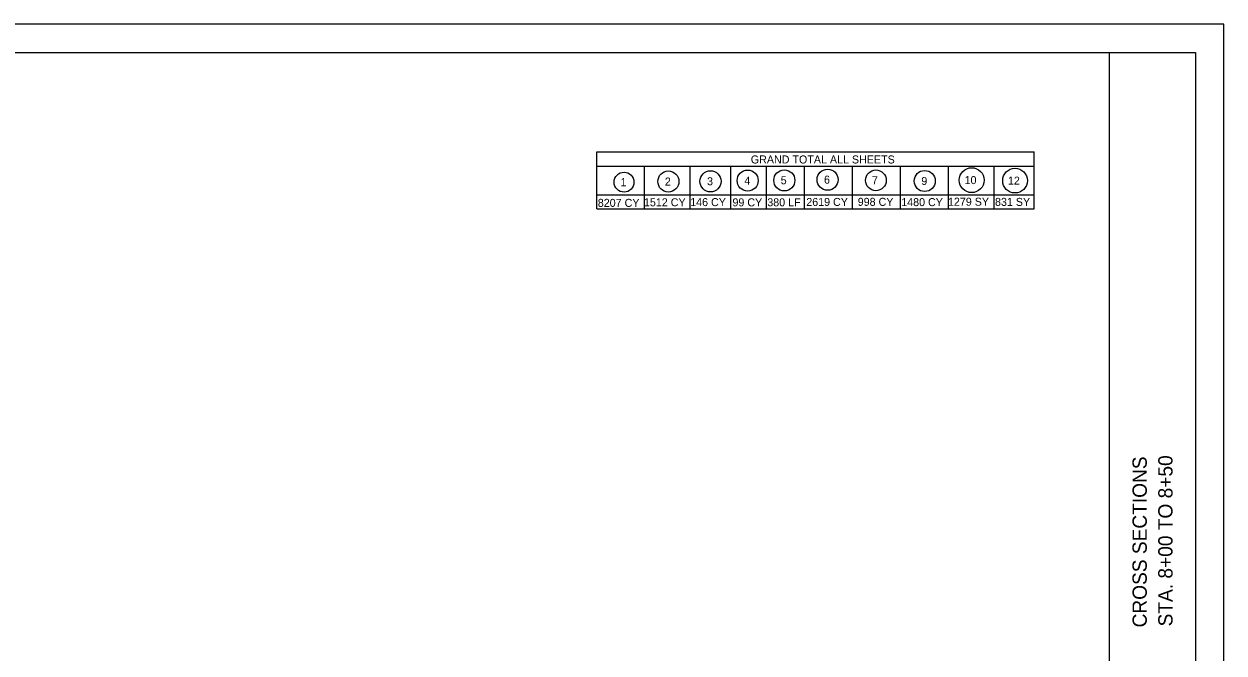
# Model space of a CAD drawing. Extents: x -31.8 to 34, y 0 to 22.
# Drawn here: x 13.01 to 34, y 11 to 22 of the extents above; entities that cross this region are included whole.
import ezdxf

# ---------------------------------------------------------------- set-up
doc = ezdxf.new("R2010")
doc.units = 0
for name, color, linetype in [('CS-ALGN-TEXT', 7, 'Continuous'), ('CS-ANNO', 7, 'Continuous'), ('CS-ANNO-MATC', 7, 'Continuous'), ('CS-ANNO-MATC-TEXT', 7, 'Continuous')]:
    doc.layers.add(name, color=color, linetype=linetype)

msp = doc.modelspace()

# ---------------------------------------------------------------- linework, layer by layer
at = {"layer": 'CS-ALGN-TEXT'}
for p, q in [((23.033, 18.765), (23.033, 19.765)), ((23.033, 19.765), (30.681, 19.765)), ((30.681, 18.765), (30.681, 19.765)), ((23.033, 19.515), (30.681, 19.515)), ((23.866, 18.764), (23.866, 19.514)), ((24.664, 18.765), (24.664, 19.515)), ((25.374, 18.765), (25.374, 19.515)), ((25.999, 18.765), (25.999, 19.515)), ((26.662, 18.765), (26.662, 19.515)), ((27.504, 18.765), (27.504, 19.515)), ((28.34, 18.765), (28.34, 19.515)), ((29.179, 18.765), (29.179, 19.515)), ((29.982, 18.765), (29.982, 19.515)), ((23.033, 19.015), (30.681, 19.015)), ((23.033, 18.765), (30.681, 18.765))]:
    msp.add_line(p, q, dxfattribs=at)
at = {"layer": 'CS-ANNO'}
msp.add_lwpolyline([(0, 0), (34, 0), (34, 22), (0, 22)], close=True, dxfattribs=at)
at = {"layer": 'CS-ANNO-MATC'}
msp.add_line((32, 0.5), (32, 21.5), dxfattribs=at)
msp.add_lwpolyline([(1.5, 21.5), (33.5, 21.5), (33.5, 0.5), (1.5, 0.5)], close=True, dxfattribs=at)
at = {"layer": 'CS-ANNO-MATC-TEXT'}
for centre, radius in [((23.507, 19.234), 0.174), ((24.282, 19.246), 0.184), ((25.019, 19.249), 0.185), ((25.669, 19.262), 0.184), ((26.31, 19.265), 0.184), ((27.067, 19.277), 0.184), ((27.912, 19.266), 0.181), ((28.766, 19.254), 0.184), ((29.587, 19.269), 0.218), ((30.345, 19.261), 0.216)]:
    msp.add_circle(centre, radius, dxfattribs=at)

# ---------------------------------------------------------------- texts
at = {"layer": 'CS-ALGN-TEXT'}
msp.add_text('GRAND TOTAL ALL SHEETS', height=0.14, dxfattribs=at).set_placement((25.724, 19.561))
for s, p in [('CROSS SECTIONS', (32.65, 11.447)), ('STA. 8+00 TO 8+50', (33.1, 11.465))]:
    msp.add_text(s, height=0.25, rotation=90, dxfattribs=at).set_placement(p)
at = {"layer": 'CS-ANNO-MATC-TEXT'}
for s, p in [('2', (24.221, 19.175)), ('3', (24.959, 19.18)), ('4', (25.612, 19.192)), ('5', (26.247, 19.197)), ('6', (27.004, 19.208)), ('7', (27.842, 19.197)), ('9', (28.706, 19.185)), ('10', (29.463, 19.2)), ('12', (30.221, 19.19)), ('1', (23.445, 19.164)), ('8207 CY', (23.048, 18.802)), ('1512 CY', (23.855, 18.812)), ('146 CY', (24.664, 18.815)), ('99 CY', (25.403, 18.811)), ('380 LF', (26.012, 18.812)), ('2619 CY', (26.694, 18.818)), ('998 CY', (27.594, 18.82)), ('1480 CY', (28.355, 18.815)), ('1279 SY', (29.172, 18.822)), ('831 SY', (29.995, 18.819))]:
    msp.add_text(s, height=0.14, dxfattribs=at).set_placement(p)

doc.saveas('drawing.dxf')
